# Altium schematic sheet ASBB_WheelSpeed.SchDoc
size A4
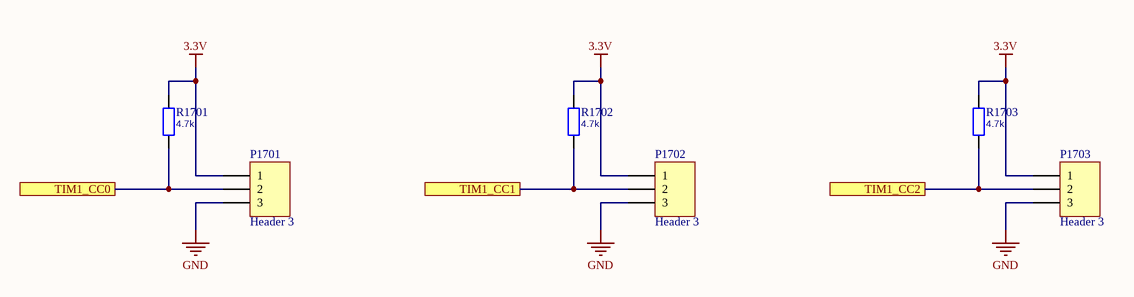
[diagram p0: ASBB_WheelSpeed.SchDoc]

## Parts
P1701  Header 3  [HDR1X3]
P1702  Header 3  [HDR1X3]
P1703  Header 3  [HDR1X3]
R1701  4.7k  [0603]
R1702  4.7k  [0603]
R1703  4.7k  [0603]

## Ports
TIM1_CC0, TIM1_CC1, TIM1_CC2

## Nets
3.3V: P1701.1 P1702.1 P1703.1 R1701.2 R1702.2 R1703.2
GND: P1701.3 P1702.3 P1703.3
TIM1_CC0: P1701.2 R1701.1 ; port TIM1_CC0
TIM1_CC1: P1702.2 R1702.1 ; port TIM1_CC1
TIM1_CC2: P1703.2 R1703.1 ; port TIM1_CC2

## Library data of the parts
P1701-P1703 = Header 3: Header, 3-Pin
R1701-R1703 = Resistor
